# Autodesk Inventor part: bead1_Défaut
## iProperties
Shininess: 64.0
Length Units: 11269
Angle Units: 11279
Time Units: 11290
Mass Units: 11283
Length Display Precision: 3
Angle Display Precision: 2
Compacted: True
Part Number: bead1_Défaut
Document SubType Name: Modeling
Created: 2006-11
Material: Par défaut
Designer: profs_sti
Density: 0.0
Volumn: 0.0
Area: 0.0
PropertySet Name: Model Information
Control State: 0
Master: False
Checked Out: False
Author: profs_sti
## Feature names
1. Base1
